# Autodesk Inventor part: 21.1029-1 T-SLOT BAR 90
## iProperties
Created: 2006-12
Part Number: 21.1029-1 T-SLOT BAR 90
Material: Steel
Document SubType Name: Modeling
Designer: Andy Moles
Mass: 54.3517 g
Surface Area: 38.9719 cm^2
Volume: 6.92378 cm^3
Density: 7.85 g/cm^3
Author: Andy Moles
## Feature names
1. Extrusion1
2. Hole1
